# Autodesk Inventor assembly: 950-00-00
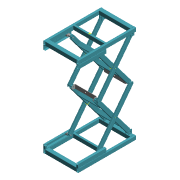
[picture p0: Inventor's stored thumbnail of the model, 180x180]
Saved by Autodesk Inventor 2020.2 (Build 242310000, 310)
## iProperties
Created: 2015-10
Part Number: 950-00-00
Document SubType Name: Assembly
Designer: F.Stasiak
Catalog Web Link: www.expertbooks.pl
Manager: www.cadconsulting.pl
Company: Fabian Stasiak CAD Consulting
Author: F.Stasiak
Subject: Zbiór ćwiczeń. Autodesk Inventor 2020. Kurs Professional
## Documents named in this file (8)
- C:\2020_Kurs_Professional\R3 Dynamika\950-00-00.iam
- C:\2020_Kurs_Professional\R3 Dynamika\Komponenty_dyn\900-01-00.iam
- C:\2020_Kurs_Professional\R3 Dynamika\Komponenty_dyn\900-03-00.iam
- C:\2020_Kurs_Professional\R3 Dynamika\Komponenty_dyn\900-04-00.iam
- C:\2020_Kurs_Professional\R3 Dynamika\Komponenty_dyn\900-02-00.iam
- C:\2020_Kurs_Professional\R3 Dynamika\Komponenty_dyn\900-05-01.ipt
- C:\2020_Kurs_Professional\R3 Dynamika\Komponenty_dyn\900-06-01.ipt
- C:\2020_Kurs_Professional\R3 Dynamika\Komponenty_dyn\900-07-02.ipt
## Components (14 placed, 7 different names)
1. 900-01-00:1 [sub-assembly] — PODNIESIENIE, Wstaw:10, Styczny:3
2. 900-02-00:1 [sub-assembly] — PODNIESIENIE, Wstaw:16, Wstaw:17
3. 900-03-00:1 [sub-assembly] — Wstaw:10, Wstaw:11, Wstaw:12, Wstaw:14, Zestawiający:23, Zestawiający:24
4. 900-03-00:2 [sub-assembly] — Wstaw:8, Wstaw:9, Wstaw:15, Zestawiający:19, Zestawiający:21, Zestawiający:22
5. 900-04-00:2 [sub-assembly] — Wstaw:17, Zestawiający:19
6. 900-04-00:6 [sub-assembly] — Wstaw:7, Wstaw:11
7. 900-04-00:4 [sub-assembly] — Wstaw:14, Wstaw:15, Wstaw:16
8. 900-04-00:5 [sub-assembly] — Wstaw:6, Wstaw:12, Zestawiający:21
9. 900-05-01:1 — Wstaw:6
10. 900-05-01:2 — Wstaw:7, Styczny:3
11. 900-06-01:1 — Wstaw:9
12. 900-06-01:2 — Wstaw:8
13. 900-07-02:1 — Zestawiający:23, Zestawiający:20, Zestawiający:24
14. 900-07-02:2 — Zestawiający:20, Zestawiający:22
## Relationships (19: Insert 11, Mate 7, Tangent 1)
- PODNIESIENIE [Mate]: 900-01-00:1 ↔ 900-02-00:1
- Styczny:3 [Tangent]: 900-01-00:1 ↔ 900-05-01:2
- Wstaw:6 [Insert]: 900-04-00:5 ↔ 900-05-01:1
- Wstaw:7 [Insert]: 900-04-00:6 ↔ 900-05-01:2
- Wstaw:8 [Insert]: 900-03-00:2 ↔ 900-06-01:2
- Wstaw:9 [Insert]: 900-03-00:2 ↔ 900-06-01:1
- Wstaw:10 [Insert]: 900-01-00:1 ↔ 900-03-00:1
- Wstaw:11 [Insert]: 900-03-00:1 ↔ 900-04-00:6
- Wstaw:12 [Insert]: 900-03-00:1 ↔ 900-04-00:5
- Wstaw:14 [Insert]: 900-03-00:1 ↔ 900-04-00:4
- Wstaw:15 [Insert]: 900-03-00:2 ↔ 900-04-00:4
- Wstaw:16 [Insert]: 900-02-00:1 ↔ 900-04-00:4
- Wstaw:17 [Insert]: 900-02-00:1 ↔ 900-04-00:2
- Zestawiający:19 [Mate]: 900-03-00:2 ↔ 900-04-00:2
- Zestawiający:23 [Mate]: 900-03-00:1 ↔ 900-07-02:1
- Zestawiający:21 [Mate]: 900-03-00:2 ↔ 900-04-00:5
- Zestawiający:20 [Mate]: 900-07-02:1 ↔ 900-07-02:2
- Zestawiający:22 [Mate]: 900-03-00:2 ↔ 900-07-02:2
- Zestawiający:24 [Mate]: 900-03-00:1 ↔ 900-07-02:1
